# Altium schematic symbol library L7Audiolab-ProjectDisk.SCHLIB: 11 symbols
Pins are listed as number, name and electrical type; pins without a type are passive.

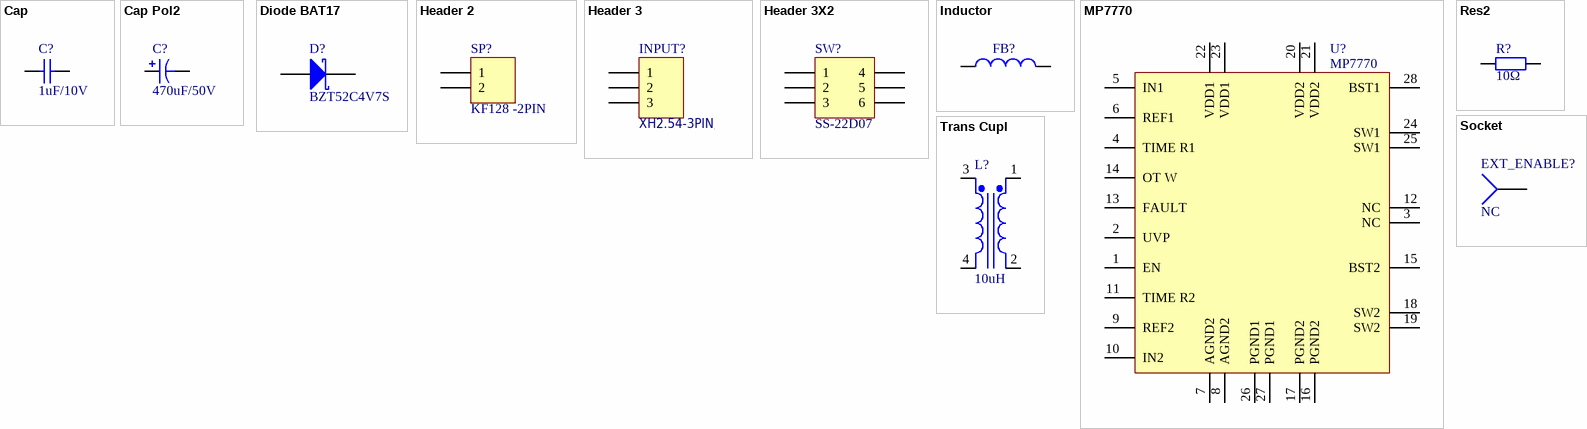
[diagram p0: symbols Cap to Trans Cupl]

## Cap
designator C?, comment 1uF/10V
Capacitor; Value: 100pF
footprint 0805_C
footprint CAPR2.54-5.1x3.2 (Capacitor, Ceramic, Thru-Hole, Dipped Radial; Body 5.1 x 3.2 mm (WxT) Pin Spacing 2.54 mm (typ))
footprint CAPR5.08-7.8x3.2 (Capacitor, Ceramic, Thru-Hole, Dipped Radial; Body 7.8 x 3.2 mm (WxT) Pin Spacing 5.08 mm (typ))
simulation model CAP (Capacitor)
signal-integrity model Cap
pins: 1, 2

## Cap Pol2
designator C?, comment 470uF/50V
Polarized Capacitor (Axial); Value: 100pF
footprint 10*17 (插件电容50V/470UF)
footprint CAPPA14.05-10.5x6.3 (Capacitor, Axial, Polarised; Body 10.5 x 6.3 mm (LxDia. max), Lead Dia. 0.6 mm (typ))
footprint CAPPA23.6-18.5x8.5 (Capacitor, Axial, Polarised; Body 18.5 x 8.5 mm (LxDia. max), Lead Dia. 0.8 mm (typ))
footprint CAPPA31.6-26.5x12.5 (Capacitor, Axial, Polarised; Body 26.5 x 12.5 mm (LxDia. max), Lead Dia. 0.8 mm (typ))
footprint CAPPA35.6-30.5x18.5 (Capacitor, Axial, Polarised; Body 30.5 x 18.5 mm (LxDia. max), Lead Dia. 0.8 mm (typ))
footprint CAPPA46.1-41x21.5 (Capacitor, Axial, Polarised; Body 41 x 21.5 mm (LxDia. max), Lead Dia. 0.8 mm (typ))
simulation model CAP (Capacitor)
signal-integrity model Cap Pol
pins: 1, 2
1 alternate drawing of the same symbol

## Diode BAT17
designator D?, comment BZT52C4V7S
Silicon RF Schottky Diode for Mixer Applications in the VHF/UHF Range; Note: Pin 2 is not connected and not drawn.
footprint LC-SOD-323
footprint SOT95P240-3L (SOT23, 3-Leads, Body 2.9x1.3mm, Pitch 0.95mm, Lead Span 2.5mm, IPC High Density)
footprint SOT95P240-3M (SOT23, 3-Leads, Body 2.9x1.3mm, Pitch 0.95mm, Lead Span 2.5mm, IPC Low Density)
simulation model D188 (DIODE)
pins: 1 A, 2

## Header 2
designator SP?, comment KF128 -2PIN
Header, 2-Pin
footprint KF128 -2PIN (5.08螺钉式PCB端子)
signal-integrity model Connector
pins: 1, 2

## Header 3
designator INPUT?, comment XH2.54-3PINֱ
Header, 3-Pin
footprint XH2.54-3PINֱ
signal-integrity model Connector
pins: 1, 2, 3

## Header 3X2
designator SW?, comment SS-22D07
Header, 3-Pin, Dual row
footprint SS-22D07 (滑动开关)
signal-integrity model Connector
pins: 1, 2, 3, 4, 5, 6

## Inductor
designator FB?
Inductor; Code_IEC: 1005; Value: 10mH
footprint 1206-R (1206贴片电阻)
footprint INDC1608L (Chip Inductor, Body 1.6x0.8mm, IPC High Density)
footprint INDC2012L (Chip Inductor, Body 2.0x1.2mm, IPC High Density)
footprint INDC0603L (Chip Inductor, Body 0.6x0.3mm, IPC High Density)
footprint INDC3216AL (Chip Inductor, Body 3.2x1.6mm, IPC High Density)
footprint INDC4532L (Chip Inductor, Body 4.5x3.2mm, IPC High Density)
simulation model INDUCTOR (Inductor)
signal-integrity model Inductor
pins: 1, 2

## MP7770
designator U?
footprint LC-TSSOP-28
pins: 1 EN, 2 UVP, 3 NC, 4 TIME R1, 5 IN1, 6 REF1, 7 AGND2, 8 AGND2, 9 REF2, 10 IN2, 11 TIME R2, 12 NC, 13 FAULT, 14 OT W, 15 BST2, 16 PGND2, 17 PGND2, 18 SW2, 19 SW2, 20 VDD2, 21 VDD2, 22 VDD1, 23 VDD1, 24 SW1, 25 SW1, 26 PGND1, 27 PGND1, 28 BST1

## Res2
designator R?, comment 10Ω
Resistor; Value: 1K
footprint 0805_R
simulation model RESISTOR (Resistor)
signal-integrity model Res
pins: 1, 2

## Socket
designator EXT_ENABLE?, comment NC
Socket
footprint PIN1 (Connector; Socket)
signal-integrity model Connector
pins: 1

## Trans Cupl
designator L?, comment 10uH
Transformer (Coupled Inductor Model)
footprint 7W14A-100M功放电感
simulation model TRANSFORMER (Transformer)
pins: 1 Sec+, 2 Sec-, 3 Pri+, 4 Pri-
